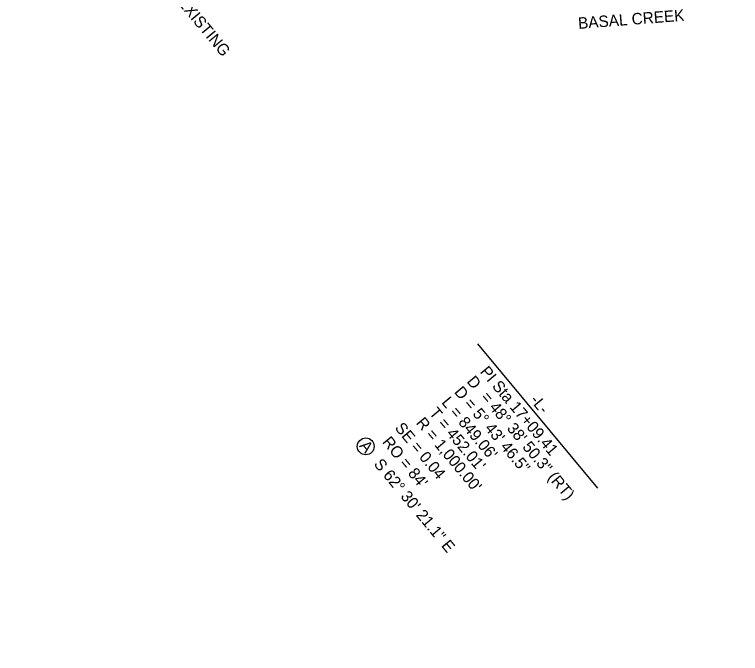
# Model space of a CAD drawing. Extents: x 2057680 to 2059216, y 687940 to 689338.
# Drawn here: x 2058310.8 to 2058753.8, y 688322.9 to 688713 of the extents above; entities that cross this region are included whole.
import ezdxf

# ---------------------------------------------------------------- set-up
doc = ezdxf.new("R2010")
doc.units = 0
for name, color, linetype in [('Cogo Default Point CELL', 7, 'Continuous'), ('COGO Default Point Elevation', 7, 'Continuous'), ('COGO Default Point Number', 7, 'Continuous'), ('Exist DTM Breakline Cogo Elevation', 7, 'Continuous'), ('Exist Structure Major Deck Tunnel Box Culvert Cogo Number', 7, 'Continuous')]:
    doc.layers.add(name, color=color, linetype=linetype)

msp = doc.modelspace()

# ---------------------------------------------------------------- linework, layer by layer
at = {"layer": 'Cogo Default Point CELL'}
msp.add_arc((2058091.57, 688086.7), 1000, 13.85856, 62.50587, dxfattribs=at)
at = {"layer": 'COGO Default Point Elevation'}
msp.add_line((2058593.38, 688511.94), (2058666.51, 688423.75), dxfattribs=at)
at = {"layer": 'COGO Default Point Number'}
msp.add_circle((2058525.12, 688449.32), 5.14, dxfattribs=at)
at = {"layer": 'Exist Structure Major Deck Tunnel Box Culvert Cogo Number'}
for radius in [1012, 986]:
    msp.add_arc((2058091.57, 688086.7), radius, 13.85856, 62.50587, dxfattribs=at)

# ---------------------------------------------------------------- texts
at = {"layer": 'COGO Default Point Elevation'}
for s, rotation, p in [('PI Sta 17+09.41', 310, (2058594.5, 688494.71)), ('D', 310, (2058586.41, 688488.8)), ('D = 5%%d 43\' 46.5"', 310, (2058578.75, 688482.37)), ('= 48%%d 38\' 50.3" (RT)', 310, (2058594.9, 688479.14)), ("L = 849.06'", 310, (2058571.03, 688476.02)), ('-L-', 309.6672, (2058625.05, 688477.36)), ("T = 452.01'", 310, (2058563.43, 688469.51)), ("R = 1,000.00'", 310, (2058555.43, 688463.49)), ('SE = 0.04', 309.7916, (2058542.53, 688460.37)), ("RO = 84'", 309.2907, (2058534.83, 688451.83))]:
    msp.add_text(s, height=7, rotation=rotation, dxfattribs=at).set_placement(p)
at = {"layer": 'COGO Default Point Number'}
for s, rotation, p in [('A', 309.4619, (2058520.9, 688449.48)), ('S 62%%d 30\' 21.1" E', 309.6618, (2058529.68, 688438.32))]:
    msp.add_text(s, height=7, rotation=rotation, dxfattribs=at).set_placement(p)
at = {"layer": 'Exist DTM Breakline Cogo Elevation'}
for s, rotation, p in [('TRANSITION PROP. SIDEWALK TO EXISTING', 309.6672, (2058309.24, 688841.63)), ('BASAL CREEK', 4.4373, (2058654.97, 688704.17))]:
    msp.add_text(s, height=7, rotation=rotation, dxfattribs=at).set_placement(p)

doc.saveas('drawing.dxf')
